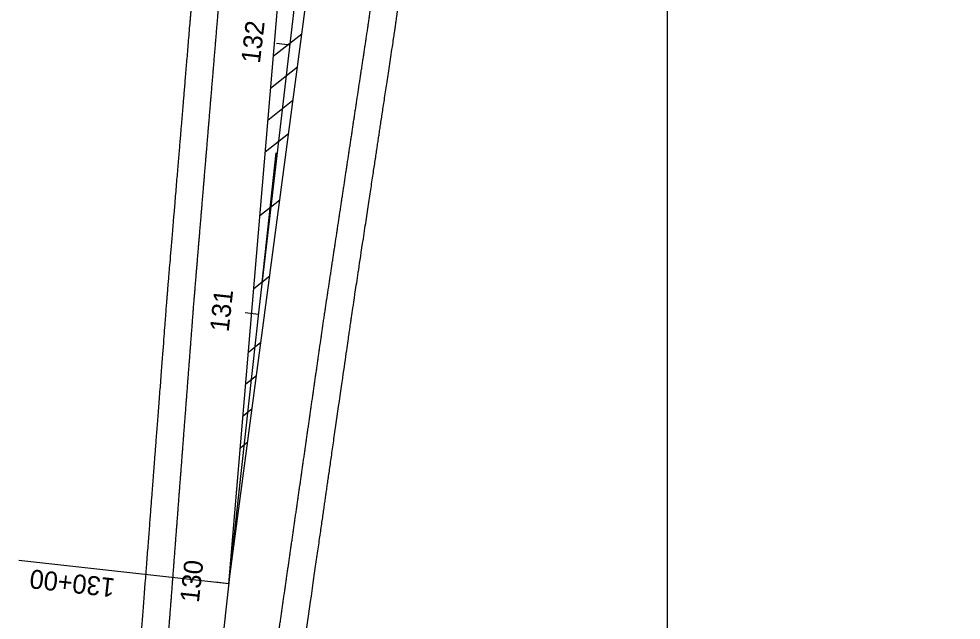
# Model space of a CAD drawing. Extents: x 2318076 to 2324211, y 613525 to 630327.
# Drawn here: x 2320430.4 to 2320778.2, y 627560.8 to 627782.7 of the extents above; entities that cross this region are included whole.
import ezdxf

# ---------------------------------------------------------------- set-up
doc = ezdxf.new("R2010")
doc.units = 0
for name, color, linetype in [('GE_P_CL_50', 7, 'Continuous'), ('PM_P_CL_Double_Solid', 7, 'Continuous'), ('PM_P_Transverse_Line', 7, 'Continuous'), ('PV_P_EOP', 7, 'Continuous'), ('PV_P_Shoulder', 7, 'Continuous'), ('SC_Scratch3', 7, 'Continuous')]:
    doc.layers.add(name, color=color, linetype=linetype)

msp = doc.modelspace()

# ---------------------------------------------------------------- linework, layer by layer
at = {"layer": 'GE_P_CL_50'}
for p, q in [((2320530.54, 627772.99), (2320525.57, 627773.57)), ((2320518.91, 627673.67), (2320513.94, 627674.22)), ((2320507.98, 627574.27), (2320430.44, 627582.8)), ((2320507.98, 627574.27), (2320503.01, 627574.82))]:
    msp.add_line(p, q, dxfattribs=at)
msp.add_lwpolyline([(2320476.3, 627307.7), (2320485.22, 627375.57), (2320502.11, 627520.92), (2320519.22, 627676.47), (2320531.82, 627783.89), (2320546.8, 627927.12), (2320554.45, 627991.34), (2320572.51, 628138.41), (2320649.52, 628804.84), (2320678.77, 629064.5), (2320690.76, 629163.78), (2320713.75, 629362.45), (2320725.26, 629461.78), (2320736.97, 629561.09), (2320748.4, 629660.43), (2320759.09, 629759.86), (2320769.62, 629859.3), (2320777.51, 629931.12), (2320778.25, 629937.84)], dxfattribs=at)
at = {"layer": 'PM_P_CL_Double_Solid'}
for q in [(2320526.13, 627789.71), (2320536.46, 627789.06)]:
    msp.add_line((2320507.98, 627574.27), q, dxfattribs=at)
at = {"layer": 'PM_P_Transverse_Line'}
for p, q in [((2320534.87, 627777.07), (2320524.36, 627768.75)), ((2320533.24, 627764.81), (2320523.37, 627757)), ((2320531.62, 627752.56), (2320522.38, 627745.25)), ((2320529.99, 627740.3), (2320521.39, 627733.49)), ((2320520.29, 627685.6), (2320525.47, 627733.32)), ((2320526.74, 627715.79), (2320519.41, 627709.99)), ((2320523.03, 627687.77), (2320517.15, 627683.11)), ((2320523.03, 627687.77), (2320517.15, 627683.11)), ((2320519.78, 627663.26), (2320515.17, 627659.61)), ((2320518.15, 627651), (2320514.18, 627647.85)), ((2320516.53, 627638.75), (2320513.19, 627636.1)), ((2320516.53, 627638.75), (2320513.5, 627636.35)), ((2320514.9, 627626.49), (2320512.2, 627624.35)), ((2320514.9, 627626.49), (2320512.2, 627624.35)), ((2320512.39, 627613.53), (2320512.15, 627613.34)), ((2320509.9, 627589.62), (2320509.38, 627589.21))]:
    msp.add_line(p, q, dxfattribs=at)
at = {"layer": 'PV_P_EOP'}
for points in [[(2320503.53, 627779.3), (2320503.61, 627780.2), (2320503.68, 627781.1), (2320503.76, 627782), (2320503.83, 627782.9), (2320503.91, 627783.8), (2320503.98, 627784.69), (2320504.06, 627785.59), (2320504.13, 627786.49), (2320504.17, 627787.04), (2320504.23, 627787.94), (2320504.3, 627788.84), (2320504.36, 627789.74), (2320504.42, 627790.64), (2320504.49, 627791.54), (2320504.55, 627792.44), (2320504.62, 627793.34), (2320504.68, 627794.24), (2320504.74, 627795.14), (2320504.81, 627796.04), (2320504.87, 627796.93), (2320504.93, 627797.83), (2320505, 627798.73), (2320505.06, 627799.63), (2320505.13, 627800.53), (2320505.19, 627801.43), (2320505.25, 627802.33), (2320505.32, 627803.23), (2320505.38, 627804.13), (2320505.45, 627805.03), (2320505.51, 627805.93), (2320505.57, 627806.83), (2320505.64, 627807.72), (2320505.7, 627808.62), (2320505.76, 627809.52), (2320505.83, 627810.42), (2320505.89, 627811.32), (2320505.96, 627812.22), (2320506.02, 627813.12), (2320506.08, 627814.02), (2320506.15, 627814.92), (2320506.21, 627815.82), (2320506.28, 627816.72), (2320506.34, 627817.62), (2320506.4, 627818.51), (2320506.47, 627819.41), (2320506.53, 627820.31), (2320506.6, 627821.21), (2320506.66, 627822.11), (2320506.72, 627823.01), (2320506.79, 627823.91), (2320506.85, 627824.81), (2320506.91, 627825.71), (2320506.98, 627826.61), (2320507.04, 627827.51), (2320507.11, 627828.4), (2320507.17, 627829.3), (2320507.23, 627830.2), (2320507.3, 627831.1), (2320507.36, 627832), (2320507.43, 627832.9), (2320507.49, 627833.8), (2320507.55, 627834.7), (2320507.62, 627835.6), (2320507.68, 627836.5), (2320507.74, 627837.4), (2320507.81, 627838.3), (2320507.87, 627839.19), (2320507.94, 627840.09), (2320508, 627840.99), (2320508.06, 627841.89), (2320508.13, 627842.79), (2320508.19, 627843.69), (2320508.26, 627844.59), (2320508.32, 627845.49)], [(2320558.27, 627772.89), (2320558.41, 627773.78), (2320558.54, 627774.67), (2320558.67, 627775.56), (2320558.81, 627776.45), (2320558.94, 627777.34), (2320559.08, 627778.24), (2320559.21, 627779.13), (2320559.35, 627780.02), (2320559.52, 627781.25), (2320559.64, 627782.15), (2320559.77, 627783.04), (2320559.89, 627783.93), (2320560.01, 627784.83), (2320560.14, 627785.72), (2320560.26, 627786.61), (2320560.38, 627787.5), (2320560.51, 627788.4), (2320560.63, 627789.29), (2320560.75, 627790.18), (2320560.88, 627791.08), (2320561, 627791.97), (2320561.12, 627792.86), (2320561.25, 627793.75), (2320561.37, 627794.65), (2320561.5, 627795.54), (2320561.62, 627796.43), (2320561.74, 627797.33), (2320561.87, 627798.22), (2320561.99, 627799.11), (2320562.11, 627800), (2320562.24, 627800.9), (2320562.36, 627801.79), (2320562.48, 627802.68), (2320562.61, 627803.58), (2320562.73, 627804.47), (2320562.86, 627805.36), (2320562.98, 627806.25), (2320563.1, 627807.15), (2320563.23, 627808.04), (2320563.35, 627808.93), (2320563.47, 627809.83), (2320563.6, 627810.72), (2320563.72, 627811.61), (2320563.84, 627812.51), (2320563.97, 627813.4), (2320564.09, 627814.29), (2320564.21, 627815.18), (2320564.34, 627816.08), (2320564.46, 627816.97), (2320564.59, 627817.86), (2320564.71, 627818.76), (2320564.83, 627819.65), (2320564.96, 627820.54), (2320565.08, 627821.43), (2320565.2, 627822.33), (2320565.33, 627823.22), (2320565.45, 627824.11), (2320565.57, 627825.01), (2320565.7, 627825.9), (2320565.82, 627826.79), (2320565.95, 627827.68), (2320566.07, 627828.58), (2320566.19, 627829.47), (2320566.32, 627830.36), (2320566.44, 627831.26), (2320566.56, 627832.15), (2320566.69, 627833.04), (2320566.81, 627833.93), (2320566.93, 627834.83), (2320567.06, 627835.72), (2320567.18, 627836.61), (2320567.3, 627837.51), (2320567.43, 627838.4), (2320567.55, 627839.29)], [(2320497.98, 627712.83), (2320498.05, 627713.73), (2320498.13, 627714.63), (2320498.2, 627715.53), (2320498.28, 627716.43), (2320498.35, 627717.32), (2320498.43, 627718.22), (2320498.5, 627719.12), (2320498.58, 627720.02), (2320498.65, 627720.92), (2320498.73, 627721.81), (2320498.8, 627722.71), (2320498.88, 627723.61), (2320498.95, 627724.51), (2320499.03, 627725.41), (2320499.11, 627726.31), (2320499.18, 627727.2), (2320499.26, 627728.1), (2320499.33, 627729), (2320499.41, 627729.9), (2320499.48, 627730.8), (2320499.56, 627731.7), (2320499.63, 627732.59), (2320499.71, 627733.49), (2320499.78, 627734.39), (2320499.86, 627735.29), (2320499.93, 627736.19), (2320500.01, 627737.09), (2320500.08, 627737.98), (2320500.16, 627738.88), (2320500.23, 627739.78), (2320500.31, 627740.68), (2320500.38, 627741.58), (2320500.46, 627742.48), (2320500.53, 627743.37), (2320500.61, 627744.27), (2320500.68, 627745.17), (2320500.76, 627746.07), (2320500.83, 627746.97), (2320500.91, 627747.86), (2320500.98, 627748.76), (2320501.06, 627749.66), (2320501.13, 627750.56), (2320501.21, 627751.46), (2320501.28, 627752.36), (2320501.36, 627753.25), (2320501.43, 627754.15), (2320501.51, 627755.05), (2320501.58, 627755.95), (2320501.66, 627756.85), (2320501.73, 627757.75), (2320501.81, 627758.64), (2320501.88, 627759.54), (2320501.96, 627760.44), (2320502.03, 627761.34), (2320502.11, 627762.24), (2320502.18, 627763.14), (2320502.26, 627764.03), (2320502.33, 627764.93), (2320502.41, 627765.83), (2320502.48, 627766.73), (2320502.56, 627767.63), (2320502.63, 627768.53), (2320502.71, 627769.42), (2320502.78, 627770.32), (2320502.86, 627771.22), (2320502.93, 627772.12), (2320503.01, 627773.02), (2320503.08, 627773.91), (2320503.16, 627774.81), (2320503.23, 627775.71), (2320503.31, 627776.61), (2320503.38, 627777.51), (2320503.46, 627778.41), (2320503.53, 627779.3)], [(2320548.3, 627706.93), (2320548.44, 627707.82), (2320548.57, 627708.72), (2320548.71, 627709.61), (2320548.84, 627710.5), (2320548.97, 627711.39), (2320549.11, 627712.28), (2320549.24, 627713.17), (2320549.38, 627714.06), (2320549.51, 627714.95), (2320549.65, 627715.85), (2320549.78, 627716.74), (2320549.92, 627717.63), (2320550.05, 627718.52), (2320550.19, 627719.41), (2320550.32, 627720.3), (2320550.46, 627721.19), (2320550.59, 627722.08), (2320550.73, 627722.98), (2320550.86, 627723.87), (2320551, 627724.76), (2320551.13, 627725.65), (2320551.26, 627726.54), (2320551.4, 627727.43), (2320551.53, 627728.32), (2320551.67, 627729.22), (2320551.8, 627730.11), (2320551.94, 627731), (2320552.07, 627731.89), (2320552.21, 627732.78), (2320552.34, 627733.67), (2320552.48, 627734.56), (2320552.61, 627735.45), (2320552.75, 627736.35), (2320552.88, 627737.24), (2320553.02, 627738.13), (2320553.15, 627739.02), (2320553.29, 627739.91), (2320553.42, 627740.8), (2320553.56, 627741.69), (2320553.69, 627742.58), (2320553.82, 627743.48), (2320553.96, 627744.37), (2320554.09, 627745.26), (2320554.23, 627746.15), (2320554.36, 627747.04), (2320554.5, 627747.93), (2320554.63, 627748.82), (2320554.77, 627749.71), (2320554.9, 627750.61), (2320555.04, 627751.5), (2320555.17, 627752.39), (2320555.31, 627753.28), (2320555.44, 627754.17), (2320555.58, 627755.06), (2320555.71, 627755.95), (2320555.85, 627756.84), (2320555.98, 627757.74), (2320556.11, 627758.63), (2320556.25, 627759.52), (2320556.38, 627760.41), (2320556.52, 627761.3), (2320556.65, 627762.19), (2320556.79, 627763.08), (2320556.92, 627763.97), (2320557.06, 627764.87), (2320557.19, 627765.76), (2320557.33, 627766.65), (2320557.46, 627767.54), (2320557.6, 627768.43), (2320557.73, 627769.32), (2320557.87, 627770.21), (2320558, 627771.11), (2320558.14, 627772), (2320558.27, 627772.89)], [(2320492.64, 627646.17), (2320492.71, 627647.07), (2320492.78, 627647.97), (2320492.84, 627648.87), (2320492.91, 627649.77), (2320492.98, 627650.66), (2320493.05, 627651.56), (2320493.12, 627652.46), (2320493.19, 627653.36), (2320493.26, 627654.26), (2320493.33, 627655.16), (2320493.39, 627656.06), (2320493.46, 627656.96), (2320493.53, 627657.86), (2320493.6, 627658.75), (2320493.67, 627659.65), (2320493.74, 627660.55), (2320493.81, 627661.45), (2320493.87, 627662.35), (2320493.94, 627663.25), (2320494.01, 627664.15), (2320494.08, 627665.05), (2320494.15, 627665.94), (2320494.22, 627666.84), (2320494.29, 627667.74), (2320494.36, 627668.64), (2320494.42, 627669.54), (2320494.49, 627670.44), (2320494.56, 627671.34), (2320494.63, 627672.24), (2320494.7, 627673.13), (2320494.77, 627674.03), (2320494.84, 627674.93), (2320494.91, 627675.83), (2320494.97, 627676.73), (2320495.04, 627677.63), (2320495.11, 627678.53), (2320495.2, 627679.6), (2320495.28, 627680.49), (2320495.35, 627681.39), (2320495.43, 627682.29), (2320495.5, 627683.19), (2320495.58, 627684.09), (2320495.65, 627684.99), (2320495.73, 627685.88), (2320495.8, 627686.78), (2320495.88, 627687.68), (2320495.95, 627688.58), (2320496.03, 627689.48), (2320496.1, 627690.38), (2320496.18, 627691.27), (2320496.25, 627692.17), (2320496.33, 627693.07), (2320496.4, 627693.97), (2320496.48, 627694.87), (2320496.55, 627695.77), (2320496.63, 627696.66), (2320496.7, 627697.56), (2320496.78, 627698.46), (2320496.85, 627699.36), (2320496.93, 627700.26), (2320497, 627701.15), (2320497.08, 627702.05), (2320497.15, 627702.95), (2320497.23, 627703.85), (2320497.3, 627704.75), (2320497.38, 627705.65), (2320497.45, 627706.54), (2320497.53, 627707.44), (2320497.6, 627708.34), (2320497.68, 627709.24), (2320497.75, 627710.14), (2320497.83, 627711.04), (2320497.9, 627711.93), (2320497.98, 627712.83)], [(2320538.58, 627641.12), (2320538.71, 627642.01), (2320538.84, 627642.9), (2320538.97, 627643.79), (2320539.1, 627644.68), (2320539.23, 627645.58), (2320539.35, 627646.47), (2320539.48, 627647.36), (2320539.61, 627648.25), (2320539.74, 627649.14), (2320539.87, 627650.04), (2320540, 627650.93), (2320540.12, 627651.82), (2320540.25, 627652.71), (2320540.38, 627653.61), (2320540.51, 627654.5), (2320540.64, 627655.39), (2320540.77, 627656.28), (2320540.89, 627657.17), (2320541.02, 627658.07), (2320541.15, 627658.96), (2320541.28, 627659.85), (2320541.41, 627660.74), (2320541.54, 627661.64), (2320541.66, 627662.53), (2320541.79, 627663.42), (2320541.92, 627664.31), (2320542.05, 627665.2), (2320542.18, 627666.1), (2320542.31, 627666.99), (2320542.44, 627667.88), (2320542.56, 627668.77), (2320542.69, 627669.67), (2320542.82, 627670.56), (2320542.95, 627671.45), (2320543.08, 627672.34), (2320543.21, 627673.23), (2320543.32, 627673.96), (2320543.45, 627674.85), (2320543.59, 627675.74), (2320543.72, 627676.63), (2320543.86, 627677.52), (2320543.99, 627678.41), (2320544.12, 627679.3), (2320544.26, 627680.19), (2320544.39, 627681.09), (2320544.53, 627681.98), (2320544.66, 627682.87), (2320544.8, 627683.76), (2320544.93, 627684.65), (2320545.07, 627685.54), (2320545.2, 627686.43), (2320545.34, 627687.33), (2320545.47, 627688.22), (2320545.61, 627689.11), (2320545.74, 627690), (2320545.88, 627690.89), (2320546.01, 627691.78), (2320546.15, 627692.67), (2320546.28, 627693.56), (2320546.42, 627694.46), (2320546.55, 627695.35), (2320546.68, 627696.24), (2320546.82, 627697.13), (2320546.95, 627698.02), (2320547.09, 627698.91), (2320547.22, 627699.8), (2320547.36, 627700.69), (2320547.49, 627701.59), (2320547.63, 627702.48), (2320547.76, 627703.37), (2320547.9, 627704.26), (2320548.03, 627705.15), (2320548.17, 627706.04), (2320548.3, 627706.93)], [(2320487.56, 627579.66), (2320487.62, 627580.56), (2320487.69, 627581.46), (2320487.76, 627582.36), (2320487.83, 627583.26), (2320487.9, 627584.16), (2320487.97, 627585.05), (2320488.04, 627585.95), (2320488.1, 627586.85), (2320488.17, 627587.75), (2320488.24, 627588.65), (2320488.31, 627589.55), (2320488.38, 627590.45), (2320488.45, 627591.35), (2320488.52, 627592.24), (2320488.59, 627593.14), (2320488.65, 627594.04), (2320488.72, 627594.94), (2320488.79, 627595.84), (2320488.86, 627596.74), (2320488.93, 627597.64), (2320489, 627598.54), (2320489.07, 627599.43), (2320489.14, 627600.33), (2320489.2, 627601.23), (2320489.27, 627602.13), (2320489.34, 627603.03), (2320489.41, 627603.93), (2320489.48, 627604.83), (2320489.55, 627605.73), (2320489.62, 627606.62), (2320489.68, 627607.52), (2320489.75, 627608.42), (2320489.82, 627609.32), (2320489.89, 627610.22), (2320489.96, 627611.12), (2320490.03, 627612.02), (2320490.1, 627612.92), (2320490.17, 627613.81), (2320490.23, 627614.71), (2320490.3, 627615.61), (2320490.37, 627616.51), (2320490.44, 627617.41), (2320490.51, 627618.31), (2320490.58, 627619.21), (2320490.65, 627620.11), (2320490.72, 627621.01), (2320490.78, 627621.9), (2320490.85, 627622.8), (2320490.92, 627623.7), (2320490.99, 627624.6), (2320491.06, 627625.5), (2320491.13, 627626.4), (2320491.2, 627627.3), (2320491.26, 627628.2), (2320491.33, 627629.09), (2320491.4, 627629.99), (2320491.47, 627630.89), (2320491.54, 627631.79), (2320491.61, 627632.69), (2320491.68, 627633.59), (2320491.75, 627634.49), (2320491.81, 627635.39), (2320491.88, 627636.28), (2320491.95, 627637.18), (2320492.02, 627638.08), (2320492.09, 627638.98), (2320492.16, 627639.88), (2320492.23, 627640.78), (2320492.29, 627641.68), (2320492.36, 627642.58), (2320492.43, 627643.47), (2320492.5, 627644.37), (2320492.57, 627645.27), (2320492.64, 627646.17)], [(2320529.08, 627575.09), (2320529.21, 627575.98), (2320529.34, 627576.88), (2320529.47, 627577.77), (2320529.6, 627578.66), (2320529.72, 627579.55), (2320529.85, 627580.44), (2320529.98, 627581.34), (2320530.11, 627582.23), (2320530.24, 627583.12), (2320530.37, 627584.01), (2320530.49, 627584.91), (2320530.62, 627585.8), (2320530.75, 627586.69), (2320530.88, 627587.58), (2320531.01, 627588.47), (2320531.14, 627589.37), (2320531.27, 627590.26), (2320531.39, 627591.15), (2320531.52, 627592.04), (2320531.65, 627592.94), (2320531.78, 627593.83), (2320531.91, 627594.72), (2320532.04, 627595.61), (2320532.16, 627596.5), (2320532.29, 627597.4), (2320532.42, 627598.29), (2320532.55, 627599.18), (2320532.68, 627600.07), (2320532.81, 627600.97), (2320532.93, 627601.86), (2320533.06, 627602.75), (2320533.19, 627603.64), (2320533.32, 627604.53), (2320533.45, 627605.43), (2320533.58, 627606.32), (2320533.7, 627607.21), (2320533.83, 627608.1), (2320533.96, 627609), (2320534.09, 627609.89), (2320534.22, 627610.78), (2320534.35, 627611.67), (2320534.47, 627612.56), (2320534.6, 627613.46), (2320534.73, 627614.35), (2320534.86, 627615.24), (2320534.99, 627616.13), (2320535.12, 627617.03), (2320535.25, 627617.92), (2320535.37, 627618.81), (2320535.5, 627619.7), (2320535.63, 627620.59), (2320535.76, 627621.49), (2320535.89, 627622.38), (2320536.02, 627623.27), (2320536.14, 627624.16), (2320536.27, 627625.06), (2320536.4, 627625.95), (2320536.53, 627626.84), (2320536.66, 627627.73), (2320536.79, 627628.62), (2320536.91, 627629.52), (2320537.04, 627630.41), (2320537.17, 627631.3), (2320537.3, 627632.19), (2320537.43, 627633.09), (2320537.56, 627633.98), (2320537.68, 627634.87), (2320537.81, 627635.76), (2320537.94, 627636.65), (2320538.07, 627637.55), (2320538.2, 627638.44), (2320538.33, 627639.33), (2320538.45, 627640.22), (2320538.58, 627641.12)], [(2320482.44, 627513.23), (2320482.51, 627514.12), (2320482.59, 627515.02), (2320482.66, 627515.92), (2320482.73, 627516.82), (2320482.8, 627517.72), (2320482.88, 627518.62), (2320482.95, 627519.52), (2320483.02, 627520.41), (2320483.09, 627521.31), (2320483.16, 627522.21), (2320483.23, 627523.04), (2320483.3, 627523.94), (2320483.37, 627524.84), (2320483.43, 627525.73), (2320483.5, 627526.63), (2320483.57, 627527.53), (2320483.64, 627528.43), (2320483.71, 627529.33), (2320483.78, 627530.23), (2320483.85, 627531.13), (2320483.91, 627532.03), (2320483.98, 627532.92), (2320484.05, 627533.82), (2320484.12, 627534.72), (2320484.19, 627535.62), (2320484.26, 627536.52), (2320484.33, 627537.42), (2320484.4, 627538.32), (2320484.46, 627539.22), (2320484.53, 627540.11), (2320484.6, 627541.01), (2320484.67, 627541.91), (2320484.74, 627542.81), (2320484.81, 627543.71), (2320484.88, 627544.61), (2320484.94, 627545.51), (2320485.01, 627546.41), (2320485.08, 627547.31), (2320485.15, 627548.2), (2320485.22, 627549.1), (2320485.29, 627550), (2320485.36, 627550.9), (2320485.43, 627551.8), (2320485.49, 627552.7), (2320485.56, 627553.6), (2320485.63, 627554.5), (2320485.7, 627555.39), (2320485.77, 627556.29), (2320485.84, 627557.19), (2320485.91, 627558.09), (2320485.98, 627558.99), (2320486.04, 627559.89), (2320486.11, 627560.79), (2320486.18, 627561.69), (2320486.25, 627562.58), (2320486.32, 627563.48), (2320486.39, 627564.38), (2320486.46, 627565.28), (2320486.52, 627566.18), (2320486.59, 627567.08), (2320486.66, 627567.98), (2320486.73, 627568.88), (2320486.8, 627569.77), (2320486.87, 627570.67), (2320486.94, 627571.57), (2320487.01, 627572.47), (2320487.07, 627573.37), (2320487.14, 627574.27), (2320487.21, 627575.17), (2320487.28, 627576.07), (2320487.35, 627576.96), (2320487.42, 627577.86), (2320487.49, 627578.76), (2320487.56, 627579.66)], [(2320519.54, 627509), (2320519.67, 627509.89), (2320519.8, 627510.78), (2320519.93, 627511.68), (2320520.06, 627512.57), (2320520.2, 627513.46), (2320520.33, 627514.35), (2320520.46, 627515.24), (2320520.59, 627516.14), (2320520.72, 627517.03), (2320520.85, 627517.92), (2320520.99, 627518.88), (2320521.12, 627519.77), (2320521.25, 627520.67), (2320521.38, 627521.56), (2320521.51, 627522.45), (2320521.64, 627523.34), (2320521.76, 627524.24), (2320521.89, 627525.13), (2320522.02, 627526.02), (2320522.15, 627526.91), (2320522.28, 627527.8), (2320522.41, 627528.7), (2320522.53, 627529.59), (2320522.66, 627530.48), (2320522.79, 627531.37), (2320522.92, 627532.27), (2320523.05, 627533.16), (2320523.18, 627534.05), (2320523.3, 627534.94), (2320523.43, 627535.83), (2320523.56, 627536.73), (2320523.69, 627537.62), (2320523.82, 627538.51), (2320523.95, 627539.4), (2320524.08, 627540.3), (2320524.2, 627541.19), (2320524.33, 627542.08), (2320524.46, 627542.97), (2320524.59, 627543.86), (2320524.72, 627544.76), (2320524.85, 627545.65), (2320524.97, 627546.54), (2320525.1, 627547.43), (2320525.23, 627548.33), (2320525.36, 627549.22), (2320525.49, 627550.11), (2320525.62, 627551), (2320525.74, 627551.89), (2320525.87, 627552.79), (2320526, 627553.68), (2320526.13, 627554.57), (2320526.26, 627555.46), (2320526.39, 627556.36), (2320526.51, 627557.25), (2320526.64, 627558.14), (2320526.77, 627559.03), (2320526.9, 627559.92), (2320527.03, 627560.82), (2320527.16, 627561.71), (2320527.28, 627562.6), (2320527.41, 627563.49), (2320527.54, 627564.38), (2320527.67, 627565.28), (2320527.8, 627566.17), (2320527.93, 627567.06), (2320528.06, 627567.95), (2320528.18, 627568.85), (2320528.31, 627569.74), (2320528.44, 627570.63), (2320528.57, 627571.52), (2320528.7, 627572.41), (2320528.83, 627573.31), (2320528.95, 627574.2), (2320529.08, 627575.09)]]:
    msp.add_spline(points, degree=3, dxfattribs=at)
at = {"layer": 'PV_P_Shoulder'}
for points, degree in [([(2320568.16, 627771.39), (2320568.37, 627772.77), (2320568.68, 627774.85), (2320569.02, 627777.09), (2320569.16, 627778.04), (2320569.21, 627778.34), (2320569.23, 627778.47), (2320569.24, 627778.52), (2320569.24, 627778.53), (2320569.24, 627778.53), (2320569.24, 627778.54), (2320569.24, 627778.57), (2320569.25, 627778.62), (2320569.26, 627778.67), (2320569.33, 627779.17), (2320569.38, 627779.55), (2320569.42, 627779.84), (2320569.42, 627779.86), (2320569.42, 627779.88), (2320569.42, 627779.88), (2320569.42, 627779.89), (2320569.43, 627779.91), (2320569.44, 627779.97), (2320569.45, 627780.11), (2320569.5, 627780.41), (2320569.58, 627781.02), (2320569.75, 627782.23), (2320570.08, 627784.65), (2320571.14, 627792.26), (2320573.63, 627810.25), (2320575.93, 627826.85), (2320577.46, 627837.92)], 3), ([(2320493.57, 627780.14), (2320493.77, 627782.51), (2320493.97, 627784.89), (2320494.16, 627787.27)], 2), ([(2320488.01, 627713.67), (2320489.87, 627735.82), (2320491.72, 627757.98), (2320493.57, 627780.14)], 2), ([(2320558.19, 627705.44), (2320561.51, 627727.42), (2320564.83, 627749.41), (2320568.16, 627771.39)], 2), ([(2320482.67, 627646.93), (2320483.09, 627652.49), (2320483.73, 627660.82), (2320484.47, 627670.55), (2320484.84, 627675.41), (2320485.03, 627677.84), (2320485.11, 627678.9), (2320485.14, 627679.25), (2320485.14, 627679.27), (2320485.14, 627679.28), (2320485.14, 627679.33), (2320485.15, 627679.41), (2320485.16, 627679.49), (2320485.17, 627679.65), (2320485.18, 627679.75), (2320485.2, 627680.04), (2320485.22, 627680.21), (2320485.23, 627680.38), (2320485.23, 627680.4), (2320485.24, 627680.42), (2320485.24, 627680.43), (2320485.24, 627680.44), (2320485.24, 627680.45), (2320485.24, 627680.51), (2320485.25, 627680.65), (2320485.28, 627680.95), (2320485.33, 627681.56), (2320485.43, 627682.77), (2320485.64, 627685.2), (2320486.04, 627690.06), (2320486.85, 627699.78), (2320487.55, 627708.11), (2320488.01, 627713.67)], 3), ([(2320548.48, 627639.69), (2320549.27, 627645.18), (2320550.46, 627653.41), (2320551.84, 627663.01), (2320552.53, 627667.82), (2320552.87, 627670.22), (2320553.03, 627671.29), (2320553.09, 627671.7), (2320553.1, 627671.77), (2320553.1, 627671.79), (2320553.1, 627671.8), (2320553.1, 627671.81), (2320553.1, 627671.82), (2320553.11, 627671.85), (2320553.12, 627671.91), (2320553.14, 627672.05), (2320553.15, 627672.14), (2320553.18, 627672.29), (2320553.19, 627672.34), (2320553.2, 627672.41), (2320553.2, 627672.43), (2320553.2, 627672.45), (2320553.2, 627672.46), (2320553.21, 627672.47), (2320553.21, 627672.5), (2320554.87, 627683.49), (2320556.53, 627694.47), (2320558.19, 627705.44)], 3), ([(2320477.58, 627580.42), (2320479.28, 627602.59), (2320480.97, 627624.76), (2320482.67, 627646.93)], 2), ([(2320538.98, 627573.67), (2320542.15, 627595.68), (2320545.31, 627617.68), (2320548.48, 627639.69)], 2), ([(2320472.47, 627514.03), (2320472.7, 627516.81), (2320472.93, 627519.57), (2320473.17, 627522.65), (2320473.2, 627523.08), (2320473.23, 627523.51), (2320473.25, 627523.68), (2320473.25, 627523.76), (2320473.27, 627524.02), (2320473.34, 627524.89), (2320473.51, 627527.13), (2320474.09, 627534.75), (2320475.47, 627552.74), (2320476.74, 627569.35), (2320477.58, 627580.42)], 3), ([(2320529.43, 627507.54), (2320529.83, 627510.28), (2320530.25, 627513.03), (2320530.7, 627516.16), (2320530.78, 627516.68), (2320530.86, 627517.21), (2320530.91, 627517.56), (2320530.93, 627517.73), (2320531.05, 627518.59), (2320531.35, 627520.65), (2320532.44, 627528.23), (2320535.02, 627546.13), (2320537.4, 627562.65), (2320538.98, 627573.67)], 3)]:
    msp.add_open_spline(points, degree=degree, dxfattribs=at)
at = {"layer": 'SC_Scratch3'}
msp.add_line((2320669.87, 614778.41), (2320669.87, 630327.22), dxfattribs=at)

# ---------------------------------------------------------------- texts
at = {"layer": 'GE_P_CL_50'}
for s, rotation, p in [('132', 83.3138, (2320519.4, 627766.04)), ('131', 83.7204, (2320507.86, 627666.96)), ('130', 83.7204, (2320496.87, 627567.07)), ('130+00', 173.7204, (2320466.19, 627576.18))]:
    msp.add_text(s, height=7, rotation=rotation, dxfattribs=at).set_placement(p)

doc.saveas('drawing.dxf')
